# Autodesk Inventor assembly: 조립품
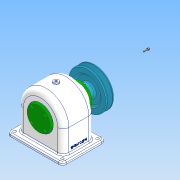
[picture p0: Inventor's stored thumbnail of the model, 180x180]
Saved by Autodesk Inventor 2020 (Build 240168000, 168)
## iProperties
Created: 2022-09
Part Number: 조립품
Document SubType Name: Assembly
Designer: user
Author: user
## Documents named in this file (16)
- C:\Users\user\Desktop\720906V1005\조립품.iam
- C:\Users\user\Desktop\720906V1005\본체.ipt
- C:\Users\user\Desktop\720906V1005\V-벨트풀리.ipt
- C:\Users\user\Desktop\720906V1005\뒤커버.ipt
- C:\Users\user\Desktop\720906V1005\멈춤나사 M4 x 10.ipt
- C:\Users\user\Desktop\720906V1005\베어링 6203.ipt
- C:\Users\user\Desktop\720906V1005\볼트 M3 x 10.ipt
- C:\Users\user\Desktop\720906V1005\스퍼기어.ipt
- C:\Users\user\Desktop\720906V1005\앞커버.ipt
- C:\Users\user\Desktop\720906V1005\오일 실 17 x 30 x 8.ipt
- C:\Users\user\Desktop\720906V1005\와셔 6 x 22.ipt
- C:\Users\user\Desktop\720906V1005\육각머리볼트 M3 x 8.ipt
- C:\Users\user\Desktop\720906V1005\축.ipt
- C:\Users\user\Desktop\720906V1005\칼라.ipt
- C:\Users\user\Desktop\720906V1005\키 5 x 5 x 18.ipt
- C:\Users\user\Desktop\720906V1005\키 6 x 6 x 22.ipt
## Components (2 placed, 2 different names)
1. V-벨트풀리:1 — 플러쉬:1
2. ISO 4762 M3 x 10:1
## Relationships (1: Flush 1)
- 플러쉬:1 [Flush]: V-벨트풀리:1
